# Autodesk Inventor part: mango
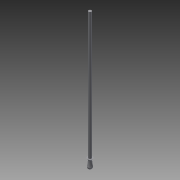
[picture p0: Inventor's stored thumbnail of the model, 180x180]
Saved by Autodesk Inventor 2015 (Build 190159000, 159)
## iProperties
Created: 2016-05
Part Number: mango
Material: Genérico
Document SubType Name: Modeling
Designer: ALEX
Density: 1 g/cm^3
Appearance: Valor por defecto
Author: ALEX
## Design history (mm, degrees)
sketch "Boceto1"
  geometry: C1 r 7.5 at (0, 0); 1 further point
  constraints: 1 centre point, 1 coincident
  dimensions: "d0" = 15 diameter of C1
extrude "Extrusión1" new body sketch "Boceto1" distance "d1" = 650; taper "d2" = 0 deg
node "Plano de trabajo1"
sketch "Boceto2"
  geometry: 1 further point
sketch "Boceto3"
  geometry: L1 (0, 0)-(0, -50); L2 (7.512, 0)-(13.518, 0); L3 (7.512, 0)-(0, 0); L4 (-7.5, 0)-(7.5, 0) reference; A1 r 12.288 centre (19.752, -10.589) between (13.518, 0) and (7.512, -11.676); A2 r 135.634 centre (143.021, -5.838) between (7.465, -10.448) and (10.266, -33.634); A3 r 12.288 centre (-19.752, -10.589) between (-7.512, -11.676) and (-7.465, -10.448); A4 r 135.634 centre (-143.021, -5.838) between (-7.488, -0.612) and (-7.512, 0); A5 r 11.402 centre (0, -38.598) between (0, -50) and (10.266, -33.634); A6 r 135.634 centre (-143.021, -5.838) between (-7.512, -11.676) and (-7.465, -10.448)
  constraints: 14 point on circle, 6 centre point, 6 end point, 4 symmetric about line, 1 collinear, 1 horizontal, 1 point on line, 1 vertical, 1 other
  dimensions: "d4" = 50 distance of L1.start L1.end
revolve "Revolución1" sketch "Boceto3" stored, may be unused: angle "d5" = 90 deg
fillet "Empalme1" dims "d6" = 2
node "Sólido1"
other parameters: "d3" = 0
